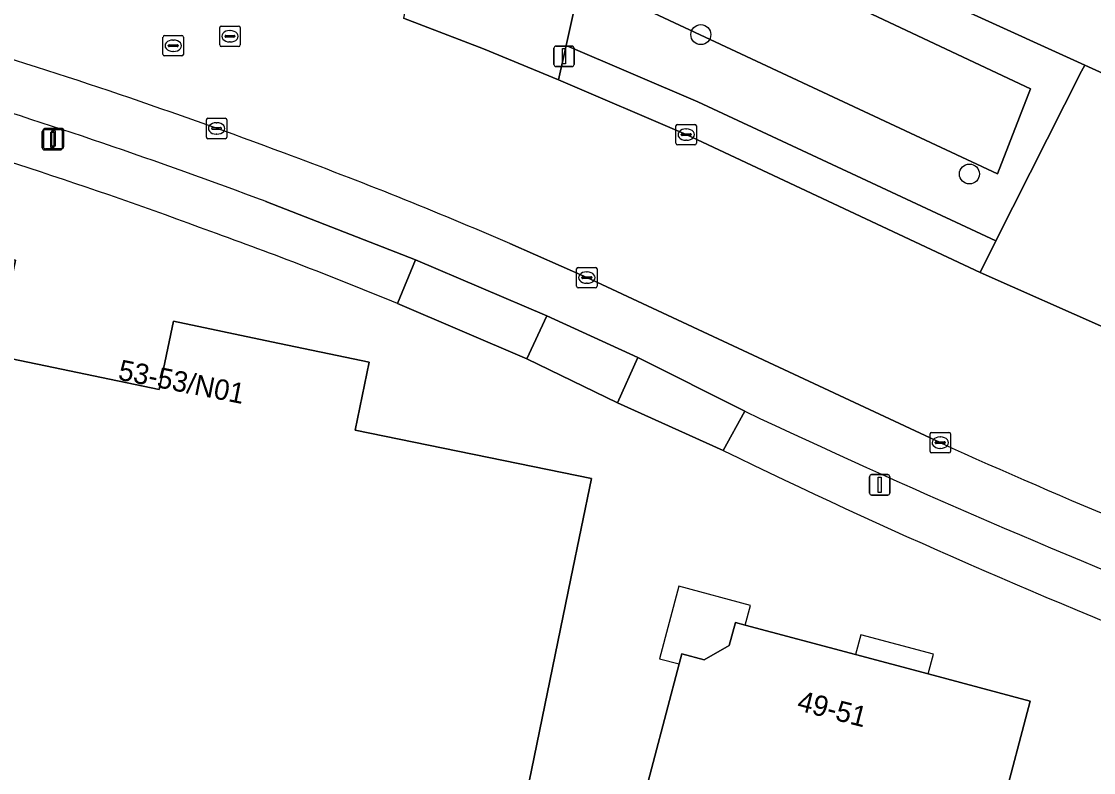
# Model space of a CAD drawing. Extents: x 157692 to 159674, y 381452 to 383291.
# Drawn here: x 158123.8 to 158176.3, y 381820.9 to 381857.7 of the extents above; entities that cross this region are included whole.
import ezdxf

# ---------------------------------------------------------------- set-up
doc = ezdxf.new("R2010")
doc.units = 0
for name, color, linetype in [('IMGEO_Boom', 7, 'Continuous'), ('IMGEO_Erf', 7, 'Continuous'), ('IMGEO_Groenvoorziening', 7, 'Continuous'), ('IMGEO_Hek', 7, 'Continuous'), ('IMGEO_Kolk', 7, 'Continuous'), ('IMGEO_Lichtmast', 7, 'Continuous'), ('IMGEO_Pand', 7, 'Continuous'), ('IMGEO_Pand_nummerreeks', 7, 'Continuous'), ('IMGEO_Pand_overbouw', 7, 'Continuous'), ('IMGEO_Parkeervlak_open', 7, 'Continuous'), ('IMGEO_Rijbaan_lokaal_gesloten', 7, 'Continuous'), ('IMGEO_Rijbaan_lokaal_open', 7, 'Continuous'), ('IMGEO_Rioolput', 7, 'Continuous'), ('IMGEO_Voetpad_open', 7, 'Continuous'), ('IMGEO_Waterloop', 7, 'Continuous')]:
    doc.layers.add(name, color=color, linetype=linetype)

msp = doc.modelspace()

# ---------------------------------------------------------------- linework, layer by layer
at = {"layer": 'IMGEO_Boom'}
for centre in [(158157.094, 381857.037), (158170.245, 381850.21)]:
    msp.add_circle(centre, 0.489, dxfattribs=at)
at = {"layer": 'IMGEO_Erf'}
for points in [[(158120.644, 381974.489), (158119.054, 381966.712), (158111.645, 381930.552), (158109.555, 381920.351), (158108.214, 381913.847), (158101.637, 381881.433), (158103.57, 381880.897), (158105.432, 381880.499), (158105.527, 381880.719), (158125.96, 381875.333), (158144.779, 381868.849), (158152.635, 381866.121), (158152.79, 381866.076), (158175.894, 381855.545), (158181.715, 381852.892), (158181.907, 381852.815), (158201.637, 381844.863), (158208.362, 381842.809), (158208.31, 381842.627), (158217.316, 381839.906), (158270.263, 381825.792)], [(158098.579, 381811.447), (158101.581, 381826.071), (158102.734, 381825.813), (158104.044, 381832.191), (158104.164, 381832.773), (158101.359, 381833.35), (158101.783, 381835.271), (158097.517, 381836.193), (158098.197, 381839.516), (158100.733, 381851.905), (158112.978, 381849.405), (158112.74, 381848.239), (158123.532, 381845.992), (158122.559, 381841.327), (158130.579, 381839.658), (158131.276, 381843.007), (158136.07, 381841.995), (158140.855, 381840.985), (158140.175, 381837.654), (158151.738, 381835.295), (158150.734, 381830.397), (158145.367, 381804.226)], [(158158.188, 381836.67), (158153.013, 381839.008), (158148.581, 381841.149), (158142.249, 381843.867)], [(158189.104, 381771.32), (158172.49, 381775.754), (158176.047, 381789.085), (158164.628, 381792.132), (158155.182, 381794.653), (158156.473, 381799.494), (158153.238, 381800.358), (158150.482, 381805.117), (158154.762, 381821.382), (158156.034, 381826.217), (158156.162, 381826.702), (158157.265, 381826.409), (158158.474, 381827.112), (158158.783, 381828.244), (158159.272, 381828.113), (158164.671, 381826.668), (158168.219, 381825.718), (158173.211, 381824.382), (158171.835, 381819.136), (158173.085, 381818.801), (158176.62, 381817.853)]]:
    msp.add_lwpolyline(points, dxfattribs=at)
for centre, radius, start, end in [((158054.025, 381634.974), 226.658, 69.58203, 74.34294), ((158058.571, 381640.219), 220.17, 67.66253, 70.21463), ((158299.7, 382126.88), 322.874, 244.00529, 248.69973)]:
    msp.add_arc(centre, radius, start, end, dxfattribs=at)
at = {"layer": 'IMGEO_Groenvoorziening'}
for points in [[(158152.79, 381866.076), (158152.635, 381866.121), (158150.495, 381856.499), (158156.953, 381853.746), (158171.542, 381846.928), (158175.726, 381855.243), (158175.894, 381855.545)], [(158152.275, 381859.287), (158153.602, 381863.648), (158173.23, 381854.387), (158171.62, 381850.221)]]:
    msp.add_lwpolyline(points, close=True, dxfattribs=at)
at = {"layer": 'IMGEO_Hek'}
msp.add_lwpolyline([(158152.635, 381866.121), (158152.79, 381866.076), (158181.715, 381852.892), (158201.637, 381844.863)], dxfattribs=at)
at = {"layer": 'IMGEO_Kolk'}
for p, q in [((158132.883, 381852.014), (158132.883, 381852.866)), ((158132.958, 381852.94), (158133.81, 381852.94)), ((158133.371, 381852.72), (158133.396, 381852.72)), ((158133.884, 381852.866), (158133.884, 381852.014)), ((158133.142, 381852.434), (158133.142, 381852.446)), ((158133.58, 381852.397), (158133.182, 381852.397)), ((158133.185, 381852.483), (158133.583, 381852.483)), ((158133.626, 381852.446), (158133.626, 381852.434)), ((158155.877, 381851.714), (158155.877, 381852.566)), ((158155.952, 381852.64), (158156.804, 381852.64)), ((158156.365, 381852.42), (158156.39, 381852.42)), ((158156.878, 381852.566), (158156.878, 381851.714)), ((158133.81, 381851.94), (158132.958, 381851.94)), ((158133.394, 381852.16), (158133.369, 381852.16)), ((158156.136, 381852.134), (158156.136, 381852.146)), ((158156.574, 381852.097), (158156.176, 381852.097)), ((158156.179, 381852.183), (158156.577, 381852.183)), ((158156.388, 381851.86), (158156.363, 381851.86)), ((158156.62, 381852.146), (158156.62, 381852.134)), ((158156.804, 381851.64), (158155.952, 381851.64)), ((158151.012, 381844.709), (158151.012, 381845.561)), ((158151.087, 381845.635), (158151.939, 381845.635)), ((158151.5, 381845.415), (158151.525, 381845.415)), ((158152.013, 381845.561), (158152.013, 381844.709)), ((158151.271, 381845.129), (158151.271, 381845.141)), ((158151.709, 381845.092), (158151.311, 381845.092)), ((158151.314, 381845.178), (158151.712, 381845.178)), ((158151.523, 381844.855), (158151.498, 381844.855)), ((158151.755, 381845.141), (158151.755, 381845.129)), ((158151.939, 381844.635), (158151.087, 381844.635)), ((158168.39, 381837.55), (158169.242, 381837.55)), ((158168.315, 381836.624), (158168.315, 381837.476)), ((158168.574, 381837.044), (158168.574, 381837.056)), ((158169.012, 381837.007), (158168.614, 381837.007)), ((158168.617, 381837.093), (158169.015, 381837.093)), ((158168.803, 381837.33), (158168.828, 381837.33)), ((158169.058, 381837.056), (158169.058, 381837.044)), ((158169.316, 381837.476), (158169.316, 381836.624)), ((158169.242, 381836.55), (158168.39, 381836.55)), ((158168.826, 381836.77), (158168.801, 381836.77))]:
    msp.add_line(p, q, dxfattribs=at)
for points in [[(158132.883, 381852.014), (158132.883, 381852.866)], [(158132.958, 381852.94), (158133.81, 381852.94)], [(158133.884, 381852.866), (158133.884, 381852.014)], [(158155.877, 381851.714), (158155.877, 381852.566)], [(158155.952, 381852.64), (158156.804, 381852.64)], [(158156.878, 381852.566), (158156.878, 381851.714)], [(158133.81, 381851.94), (158132.958, 381851.94)], [(158156.804, 381851.64), (158155.952, 381851.64)], [(158151.012, 381844.709), (158151.012, 381845.561)], [(158151.087, 381845.635), (158151.939, 381845.635)], [(158152.013, 381845.561), (158152.013, 381844.709)], [(158151.939, 381844.635), (158151.087, 381844.635)], [(158168.39, 381837.55), (158169.242, 381837.55)], [(158168.315, 381836.624), (158168.315, 381837.476)], [(158169.316, 381837.476), (158169.316, 381836.624)], [(158169.242, 381836.55), (158168.39, 381836.55)]]:
    msp.add_lwpolyline(points, dxfattribs=at)
for centre, radius, start, end in [((158132.96, 381852.864), 0.0765, 91.552, 178.448), ((158132.96, 381852.864), 0.0765, 91.552, 178.448), ((158133.808, 381852.864), 0.0765, 1.552, 88.448), ((158133.808, 381852.864), 0.0765, 1.552, 88.448), ((158133.182, 381852.443), 0.0403, 85.8775, 175.7526), ((158133.179, 381852.433), 0.0366, 178.938, 274.7102), ((158133.583, 381852.44), 0.043, 264.8664, 352.4533), ((158133.587, 381852.445), 0.0386, 1.7309, 96.639), ((158155.954, 381852.564), 0.0765, 91.552, 178.448), ((158155.954, 381852.564), 0.0765, 91.552, 178.448), ((158156.802, 381852.564), 0.0765, 1.552, 88.448), ((158156.802, 381852.564), 0.0765, 1.552, 88.448), ((158132.96, 381852.016), 0.0765, 181.552, 268.448), ((158132.96, 381852.016), 0.0765, 181.552, 268.448), ((158133.808, 381852.016), 0.0765, 271.552, 358.448), ((158133.808, 381852.016), 0.0765, 271.552, 358.448), ((158155.954, 381851.716), 0.0765, 181.552, 268.448), ((158155.954, 381851.716), 0.0765, 181.552, 268.448), ((158156.176, 381852.143), 0.0403, 85.8775, 175.7526), ((158156.173, 381852.133), 0.0366, 178.938, 274.7102), ((158156.577, 381852.14), 0.043, 264.8664, 352.4533), ((158156.581, 381852.145), 0.0386, 1.7309, 96.639), ((158156.802, 381851.716), 0.0765, 271.552, 358.448), ((158156.802, 381851.716), 0.0765, 271.552, 358.448), ((158151.089, 381845.559), 0.0765, 91.552, 178.448), ((158151.089, 381845.559), 0.0765, 91.552, 178.448), ((158151.937, 381845.559), 0.0765, 1.552, 88.448), ((158151.937, 381845.559), 0.0765, 1.552, 88.448), ((158151.311, 381845.138), 0.0403, 85.8775, 175.7526), ((158151.308, 381845.128), 0.0366, 178.938, 274.7102), ((158151.712, 381845.135), 0.043, 264.8664, 352.4533), ((158151.716, 381845.14), 0.0386, 1.7309, 96.639), ((158151.089, 381844.711), 0.0765, 181.552, 268.448), ((158151.089, 381844.711), 0.0765, 181.552, 268.448), ((158151.937, 381844.711), 0.0765, 271.552, 358.448), ((158151.937, 381844.711), 0.0765, 271.552, 358.448), ((158168.392, 381837.474), 0.0765, 91.552, 178.448), ((158168.392, 381837.474), 0.0765, 91.552, 178.448), ((158169.24, 381837.474), 0.0765, 1.552, 88.448), ((158169.24, 381837.474), 0.0765, 1.552, 88.448), ((158168.614, 381837.053), 0.0403, 85.8775, 175.7526), ((158168.611, 381837.043), 0.0366, 178.938, 274.7102), ((158169.015, 381837.05), 0.043, 264.8664, 352.4533), ((158169.019, 381837.055), 0.0386, 1.7309, 96.639), ((158168.392, 381836.626), 0.0765, 181.552, 268.448), ((158168.392, 381836.626), 0.0765, 181.552, 268.448), ((158169.24, 381836.626), 0.0765, 271.552, 358.448), ((158169.24, 381836.626), 0.0765, 271.552, 358.448)]:
    msp.add_arc(centre, radius, start, end, dxfattribs=at)
for centre, major_axis, ratio, start_param, end_param in [((158133.37, 381852.44), (-0.387, 0.002), 0.722429, 4.712389, 7.853982), ((158133.395, 381852.44), (-0.39, 0.002), 0.717154, 1.570796, 4.712389), ((158156.364, 381852.14), (-0.387, 0.002), 0.722429, 4.712389, 7.853982), ((158156.389, 381852.14), (-0.39, 0.002), 0.717154, 1.570796, 4.712389), ((158151.499, 381845.135), (-0.387, 0.002), 0.722429, 4.712389, 7.853982), ((158151.524, 381845.135), (-0.39, 0.002), 0.717154, 1.570796, 4.712389), ((158168.802, 381837.05), (-0.387, 0.002), 0.722429, 4.712389, 7.853982), ((158168.827, 381837.05), (-0.39, 0.002), 0.717154, 1.570796, 4.712389)]:
    msp.add_ellipse(centre, major_axis=major_axis, ratio=ratio, start_param=start_param, end_param=end_param, dxfattribs=at)
at = {"layer": 'IMGEO_Lichtmast'}
for p, q in [((158150, 381856.475), (158150.79, 381856.475)), ((158150.79, 381856.475), (158150, 381856.475)), ((158149.9, 381855.575), (158149.9, 381856.375)), ((158149.9, 381856.375), (158149.9, 381855.575)), ((158150.89, 381856.375), (158150.89, 381855.575)), ((158150.89, 381855.575), (158150.89, 381856.375)), ((158150.79, 381855.475), (158150, 381855.475)), ((158150, 381855.475), (158150.79, 381855.475)), ((158124.849, 381851.49), (158124.849, 381852.29)), ((158124.849, 381852.29), (158124.849, 381851.49)), ((158124.905, 381851.546), (158124.905, 381852.346)), ((158124.905, 381852.346), (158124.905, 381851.546)), ((158124.949, 381852.39), (158125.739, 381852.39)), ((158125.739, 381852.39), (158124.949, 381852.39)), ((158125.005, 381852.446), (158125.795, 381852.446)), ((158125.795, 381852.446), (158125.005, 381852.446)), ((158125.839, 381852.29), (158125.839, 381851.49)), ((158125.839, 381851.49), (158125.839, 381852.29)), ((158125.895, 381852.346), (158125.895, 381851.546)), ((158125.895, 381851.546), (158125.895, 381852.346)), ((158125.739, 381851.39), (158124.949, 381851.39)), ((158124.949, 381851.39), (158125.739, 381851.39)), ((158125.795, 381851.446), (158125.005, 381851.446)), ((158125.005, 381851.446), (158125.795, 381851.446)), ((158165.455, 381835.482), (158166.245, 381835.482)), ((158166.245, 381835.482), (158165.455, 381835.482)), ((158165.355, 381834.582), (158165.355, 381835.382)), ((158165.355, 381835.382), (158165.355, 381834.582)), ((158166.345, 381835.382), (158166.345, 381834.582)), ((158166.345, 381834.582), (158166.345, 381835.382)), ((158166.245, 381834.482), (158165.455, 381834.482)), ((158165.455, 381834.482), (158166.245, 381834.482))]:
    msp.add_line(p, q, dxfattribs=at)
for points in [[(158150.32, 381856.35), (158150.47, 381856.35), (158150.47, 381855.6), (158150.32, 381855.6), (158150.32, 381856.35)], [(158125.269, 381852.265), (158125.419, 381852.265), (158125.419, 381851.515), (158125.269, 381851.515), (158125.269, 381852.265)], [(158125.325, 381852.321), (158125.475, 381852.321), (158125.475, 381851.571), (158125.325, 381851.571), (158125.325, 381852.321)], [(158165.775, 381835.357), (158165.925, 381835.357), (158165.925, 381834.607), (158165.775, 381834.607), (158165.775, 381835.357)]]:
    msp.add_lwpolyline(points, dxfattribs=at)
for centre, start, end in [((158150, 381856.375), 90, 180), ((158150, 381856.375), 90, 180), ((158150.79, 381856.375), 0, 90), ((158150.79, 381856.375), 360, 90), ((158150, 381855.575), 180, 270), ((158150, 381855.575), 180, 270), ((158150.79, 381855.575), 270, 0), ((158150.79, 381855.575), 270, 0), ((158124.949, 381852.29), 90, 180), ((158124.949, 381852.29), 90, 180), ((158125.005, 381852.346), 90, 180), ((158125.005, 381852.346), 90, 180), ((158125.739, 381852.29), 0, 90), ((158125.739, 381852.29), 360, 90), ((158125.795, 381852.346), 0, 90), ((158125.795, 381852.346), 360, 90), ((158124.949, 381851.49), 180, 270), ((158124.949, 381851.49), 180, 270), ((158125.005, 381851.546), 180, 270), ((158125.005, 381851.546), 180, 270), ((158125.739, 381851.49), 270, 0), ((158125.739, 381851.49), 270, 0), ((158125.795, 381851.546), 270, 0), ((158125.795, 381851.546), 270, 0), ((158165.455, 381835.382), 90, 180), ((158165.455, 381835.382), 90, 180), ((158166.245, 381835.382), 0, 90), ((158166.245, 381835.382), 360, 90), ((158165.455, 381834.582), 180, 270), ((158165.455, 381834.582), 180, 270), ((158166.245, 381834.582), 270, 0), ((158166.245, 381834.582), 270, 0)]:
    msp.add_arc(centre, 0.1, start, end, dxfattribs=at)
at = {"layer": 'IMGEO_Pand'}
msp.add_lwpolyline([(158145.367, 381804.226), (158150.734, 381830.397), (158151.738, 381835.295), (158140.175, 381837.654), (158140.855, 381840.985), (158136.07, 381841.995), (158131.276, 381843.007), (158130.579, 381839.658), (158122.559, 381841.327), (158123.532, 381845.992), (158112.74, 381848.239), (158112.978, 381849.405), (158100.733, 381851.905), (158098.197, 381839.516), (158097.517, 381836.193), (158101.783, 381835.271), (158101.359, 381833.35), (158104.164, 381832.773), (158104.044, 381832.191), (158102.734, 381825.813), (158101.581, 381826.071), (158098.579, 381811.447)], dxfattribs=at)
msp.add_lwpolyline([(158164.628, 381792.132), (158171.835, 381819.136), (158173.211, 381824.382), (158168.219, 381825.718), (158164.671, 381826.668), (158159.272, 381828.113), (158158.783, 381828.244), (158158.474, 381827.112), (158157.265, 381826.409), (158156.162, 381826.702), (158156.034, 381826.217), (158154.762, 381821.382), (158150.482, 381805.117), (158153.238, 381800.358), (158156.473, 381799.494), (158155.182, 381794.653)], close=True, dxfattribs=at)
at = {"layer": 'IMGEO_Pand_overbouw'}
for points in [[(158159.272, 381828.113), (158159.526, 381829.069), (158156.011, 381830.016), (158155.075, 381826.455), (158156.034, 381826.217), (158156.162, 381826.702), (158157.265, 381826.409), (158158.474, 381827.112), (158158.783, 381828.244)], [(158164.671, 381826.668), (158168.219, 381825.718), (158168.477, 381826.689), (158164.93, 381827.63)]]:
    msp.add_lwpolyline(points, close=True, dxfattribs=at)
at = {"layer": 'IMGEO_Parkeervlak_open'}
for points in [[(158135.804, 381848.857), (158143.124, 381846.013), (158149.548, 381843.263), (158154.003, 381841.223), (158159.249, 381838.585)], [(158168.817, 381837.051), (158151.513, 381845.136), (158147.745, 381846.806)]]:
    msp.add_lwpolyline(points, dxfattribs=at)
for centre, radius, start, end in [((158042.286, 381599.33), 269.011, 69.45154, 73.10364), ((158040.633, 381595.569), 270.578, 69.40662, 72.99933), ((158056.18, 381634.171), 231.512, 66.70229, 69.64477), ((158324.825, 382189.32), 387.854, 244.72884, 248.6019), ((158293.532, 382111.805), 301.735, 245.58593, 253.34762)]:
    msp.add_arc(centre, radius, start, end, dxfattribs=at)
at = {"layer": 'IMGEO_Rijbaan_lokaal_gesloten'}
for points in [[(158170.769, 381845.392), (158156.373, 381852.139), (158150.122, 381854.82), (158146.45, 381856.345), (158142.538, 381857.841)], [(158147.745, 381846.806), (158151.513, 381845.136), (158168.817, 381837.051)], [(158178.653, 381841.845), (158176.956, 381842.64), (158170.769, 381845.392)]]:
    msp.add_lwpolyline(points, dxfattribs=at)
for centre, radius, start, end in [((158042.286, 381599.33), 269.011, 69.45154, 73.10364), ((158056.18, 381634.171), 231.512, 66.70229, 69.64477), ((158293.532, 382111.805), 301.735, 245.58593, 253.34762)]:
    msp.add_arc(centre, radius, start, end, dxfattribs=at)
at = {"layer": 'IMGEO_Rijbaan_lokaal_open'}
for points in [[(158144.779, 381868.849), (158142.538, 381857.841), (158146.45, 381856.345), (158150.122, 381854.82), (158150.495, 381856.499), (158152.635, 381866.121)], [(158181.717, 381852.408), (158181.907, 381852.815), (158181.715, 381852.892), (158175.894, 381855.545), (158175.726, 381855.243), (158171.542, 381846.928), (158170.769, 381845.392), (158176.956, 381842.64)]]:
    msp.add_lwpolyline(points, close=True, dxfattribs=at)
at = {"layer": 'IMGEO_Rioolput'}
for p, q in [((158133.613, 381857.457), (158134.465, 381857.457)), ((158130.761, 381856.068), (158130.761, 381856.92)), ((158130.836, 381856.994), (158131.688, 381856.994)), ((158131.762, 381856.92), (158131.762, 381856.068)), ((158133.538, 381856.531), (158133.538, 381857.383)), ((158133.797, 381856.951), (158133.797, 381856.963)), ((158134.235, 381856.914), (158133.837, 381856.914)), ((158133.84, 381857), (158134.238, 381857)), ((158134.026, 381857.237), (158134.051, 381857.237)), ((158134.281, 381856.963), (158134.281, 381856.951)), ((158134.539, 381857.383), (158134.539, 381856.531)), ((158131.02, 381856.488), (158131.02, 381856.5)), ((158131.458, 381856.451), (158131.06, 381856.451)), ((158131.063, 381856.537), (158131.461, 381856.537)), ((158131.249, 381856.774), (158131.274, 381856.774)), ((158131.504, 381856.5), (158131.504, 381856.488)), ((158134.465, 381856.457), (158133.613, 381856.457)), ((158134.049, 381856.677), (158134.024, 381856.677)), ((158131.688, 381855.994), (158130.836, 381855.994)), ((158131.272, 381856.214), (158131.247, 381856.214))]:
    msp.add_line(p, q, dxfattribs=at)
for points in [[(158133.613, 381857.457), (158134.465, 381857.457)], [(158130.761, 381856.068), (158130.761, 381856.92)], [(158130.836, 381856.994), (158131.688, 381856.994)], [(158131.762, 381856.92), (158131.762, 381856.068)], [(158133.538, 381856.531), (158133.538, 381857.383)], [(158134.539, 381857.383), (158134.539, 381856.531)], [(158134.465, 381856.457), (158133.613, 381856.457)], [(158131.688, 381855.994), (158130.836, 381855.994)]]:
    msp.add_lwpolyline(points, dxfattribs=at)
for centre, radius, start, end in [((158133.615, 381857.381), 0.0765, 91.552, 178.448), ((158133.615, 381857.381), 0.0765, 91.552, 178.448), ((158134.463, 381857.381), 0.0765, 1.552, 88.448), ((158134.463, 381857.381), 0.0765, 1.552, 88.448), ((158130.838, 381856.918), 0.0765, 91.552, 178.448), ((158130.838, 381856.918), 0.0765, 91.552, 178.448), ((158131.686, 381856.918), 0.0765, 1.552, 88.448), ((158131.686, 381856.918), 0.0765, 1.552, 88.448), ((158133.837, 381856.96), 0.0403, 85.8775, 175.7526), ((158133.834, 381856.95), 0.0366, 178.938, 274.7102), ((158134.238, 381856.957), 0.043, 264.8664, 352.4533), ((158134.242, 381856.962), 0.0386, 1.7309, 96.639), ((158131.06, 381856.497), 0.0403, 85.8775, 175.7526), ((158131.057, 381856.487), 0.0366, 178.938, 274.7102), ((158131.461, 381856.494), 0.043, 264.8664, 352.4533), ((158131.465, 381856.499), 0.0386, 1.7309, 96.639), ((158133.615, 381856.533), 0.0765, 181.552, 268.448), ((158133.615, 381856.533), 0.0765, 181.552, 268.448), ((158134.463, 381856.533), 0.0765, 271.552, 358.448), ((158134.463, 381856.533), 0.0765, 271.552, 358.448), ((158130.838, 381856.07), 0.0765, 181.552, 268.448), ((158130.838, 381856.07), 0.0765, 181.552, 268.448), ((158131.686, 381856.07), 0.0765, 271.552, 358.448), ((158131.686, 381856.07), 0.0765, 271.552, 358.448)]:
    msp.add_arc(centre, radius, start, end, dxfattribs=at)
for centre, major_axis, ratio, start_param, end_param in [((158134.025, 381856.957), (-0.387, 0.002), 0.722429, 4.712389, 7.853982), ((158134.05, 381856.957), (-0.39, 0.002), 0.717154, 1.570796, 4.712389), ((158131.248, 381856.494), (-0.387, 0.002), 0.722429, 4.712389, 7.853982), ((158131.273, 381856.494), (-0.39, 0.002), 0.717154, 1.570796, 4.712389)]:
    msp.add_ellipse(centre, major_axis=major_axis, ratio=ratio, start_param=start_param, end_param=end_param, dxfattribs=at)
at = {"layer": 'IMGEO_Voetpad_open'}
for points in [[(158171.542, 381846.928), (158156.953, 381853.746), (158150.495, 381856.499), (158150.122, 381854.82), (158156.373, 381852.139), (158170.769, 381845.392)], [(158148.581, 381841.149), (158149.548, 381843.263), (158143.124, 381846.013), (158142.249, 381843.867)], [(158153.013, 381839.008), (158154.003, 381841.223), (158149.548, 381843.263), (158148.581, 381841.149)], [(158158.188, 381836.67), (158159.249, 381838.585), (158154.003, 381841.223), (158153.013, 381839.008)]]:
    msp.add_lwpolyline(points, close=True, dxfattribs=at)
for points in [[(158142.249, 381843.867), (158143.124, 381846.013), (158135.804, 381848.857)], [(158159.249, 381838.585), (158158.188, 381836.67)]]:
    msp.add_lwpolyline(points, dxfattribs=at)
for centre, radius, start, end in [((158040.633, 381595.569), 270.578, 69.40662, 72.99933), ((158054.025, 381634.974), 226.658, 69.58203, 74.34294), ((158058.571, 381640.219), 220.17, 67.66253, 70.21463), ((158324.825, 382189.32), 387.854, 244.72884, 248.6019), ((158299.7, 382126.88), 322.874, 244.00529, 248.69973)]:
    msp.add_arc(centre, radius, start, end, dxfattribs=at)
at = {"layer": 'IMGEO_Waterloop'}
msp.add_lwpolyline([(158171.62, 381850.221), (158173.23, 381854.387), (158153.602, 381863.648), (158152.275, 381859.287)], close=True, dxfattribs=at)

# ---------------------------------------------------------------- texts
at = {"layer": 'IMGEO_Pand_nummerreeks'}
for s, rotation, p in [('53-53/N01', 348.8785, (158128.518, 381840.145)), ('49-51', 345.5241, (158161.754, 381823.953))]:
    msp.add_text(s, height=1, rotation=rotation, dxfattribs=at).set_placement(p)

doc.saveas('drawing.dxf')
